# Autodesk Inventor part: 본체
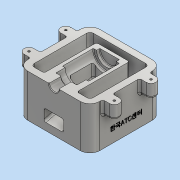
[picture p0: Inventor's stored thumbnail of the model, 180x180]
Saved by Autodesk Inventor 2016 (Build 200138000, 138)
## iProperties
Created: 2018-01
Part Number: 본체
Material: 알루미늄 6061
Document SubType Name: Modeling
Designer: Administrator
Density: 2.7 g/cm^3
Appearance: 알루미늄 - 평지
Author: Administrator
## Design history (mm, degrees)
sketch "스케치1"
  geometry: L1 (-55, 55)-(55, 55); L2 (55, 55)-(55, -55); L3 (55, -55)-(-55, -55); L4 (-55, -55)-(-55, 55); L5 (-55, 55)-(55, -55); L6 (55, 55)-(-55, -55); 1 further point
  constraints: 12 end point, 2 midpoint, 2 parallel, 1 horizontal, 1 perpendicular
  dimensions: "d0" = 110 distance of L1.start L1.end; "d1" = 110 distance of L1.end L2.end
extrude "돌출1" new body sketch "스케치1" distance "d2" = 65; taper "d3" = 0 deg
feature "쉘1" dims "d4" = 10
sketch "스케치2"
  geometry: L1 (-45, 0)-(-45, 65) reference; L2 (-45, 8.564)-(35, 30); L3 (35, 30)-(35, 65); L4 (-45, 65)-(45, 65) reference; L5 (35, 65)-(-45, 65); L6 (-45, 65)-(-45, 8.564); L7 (45, 0)-(-45, 0) reference; L8 (55, 0)-(55, 65) reference; 1 further point
  constraints: 8 end point, 1 collinear, 1 parallel, 1 perpendicular, 1 point on line
  dimensions: "d5" = 30 distance from line of L7 L2.end; "d6" = 105 deg angle of L2 L1; "d7" = 20 distance between parallel lines of L8 L3
extrude "돌출2" join sketch "스케치2" stored distance "d8" = 50; taper "d9" = 0 deg
sketch "스케치3"
  geometry: L1 (-55, -55)-(55, -55) reference; L2 (0, -55)-(0, 30); L3 (0, 30)-(-15, 30); L4 (-15, 30)-(-15, 25); L5 (-15, 25)-(-20, 25); L6 (-20, 25)-(-20, -22); L7 (-20, -22)-(-16, -22); L8 (-16, -22)-(-16, -36); L9 (-16, -36)-(-7.5, -36); L10 (-7.5, -36)-(-7.5, -55); L11 (0, -55)-(-7.5, -55); 1 further point
  constraints: 20 end point, 9 perpendicular, 1 midpoint, 1 point on line, 1 vertical
  dimensions: "d10" = 30 diameter of L3.end L2; "d11" = 15 diameter of L10 L2; "d12" = 19 distance of L9.end L10.end; "d13" = 14 distance of L7.end L8.end; "d14" = 47 distance of L5.end L6.end; "d15" = 5 distance of L3.end L4.end; "d16" = 40 diameter of L6 L2; "d17" = 32 diameter of L8 L2
revolve "회전1" sketch "스케치3" stored, may be unused: angle "d18" = 90 deg
sketch "스케치5"
  geometry: L1 (-55, 0)-(-55, 65) reference; L2 (-55, 11.061)-(20, 31.157); L3 (20, 31.157)-(20, 65); L4 (-55, 29.061)-(-17, 39.243); L5 (-17, 39.243)-(-17, 65); L6 (35, 30)-(-45, 8.564) reference; L7 (-45, 65)-(35, 65) reference; L8 (25, 65)-(25, 50) reference; 1 further point
  constraints: 8 end point, 4 point on line, 3 parallel, 1 vertical
  dimensions: "d19" = 5 distance between parallel lines of L6 L2; "d20" = 18 distance of L2.start L4.start; "d21" = 37 distance between parallel lines of L3 L5; "d25" = 5 distance from line of L8 L3.end
extrude "돌출3" cut sketch "스케치5" stored distance "d23" = 30; taper "d24" = 0 deg
sketch "스케치6"
  geometry: L1 (-55, 55)-(-55, -55) reference; L2 (-55, -55)-(-7.5, -55) reference; L3 (-55, -35.5)-(-65, -35.5); L4 (-65, -35.5)-(-65, -20.5); L5 (-65, -20.5)-(-55, -20.5); L6 (-55, -20.5)-(-55, -35.5); A1 r 7.5 centre (-65, -28) between (-65, -20.5) and (-65, -35.5); 1 further point
  constraints: 8 end point, 2 parallel, 2 point on circle, 1 centre point, 1 horizontal, 1 midpoint, 1 perpendicular, 1 point on line
  dimensions: "d26" = 27 distance from line of L2 A1.centre; "d27" = 10 distance of L5.end L4.end; "d28" = 7.5 radius of A1
extrude "돌출4" join sketch "스케치6" distance "d29" = 20; taper "d30" = 0 deg
hole "구멍1" diameter "d33" = 3.242; stored, may be unused: countersink angle "d37" = 90 deg, drill point angle "d39" = 118 deg; dims "d31" = 10, "d32" = 10, "d34" = 9, "d35" = 4, "d36" = 2, "d38" = 11
fillet "모깎기1" dims "d43" = 5
fillet "모깎기2" dims "d44" = 15
sketch "스케치7"
  geometry: L1 (65, 75.5)-(65, 60.5) reference; L2 (0, -34.5)-(65, -34.5) reference; 2 further points
  constraints: 1 other
  dimensions: "d45" = 20 distance from line of L1 point (45, 20.5); "d46" = 55 distance from line of L2 point (45, 20.5)
feature "엠보싱1" sketch "스케치7" dims "d0" = 110, "d1" = 110, "d47" = 0.5, "d48" = 0
fillet "모깎기4" dims "d53" = 3
fillet "모깎기5" dims "d54" = 3
fillet "모깎기6" dims "d55" = 3
fillet "모깎기11" dims "d60" = 3
fillet "모깎기12" dims "d61" = 3
fillet "모깎기16" dims "d65" = 1
chamfer "모따기2" distance "d66" = 1; stored, may be unused: second distance "d67" = 2, angle "d68" = 45 deg
fillet "모깎기17" dims "d69" = 3
fillet "모깎기18" dims "d70" = 3
node "솔리드1"
pattern_linear "직사각형 패턴1" dims "d42" = 56
mirror "대칭1"
